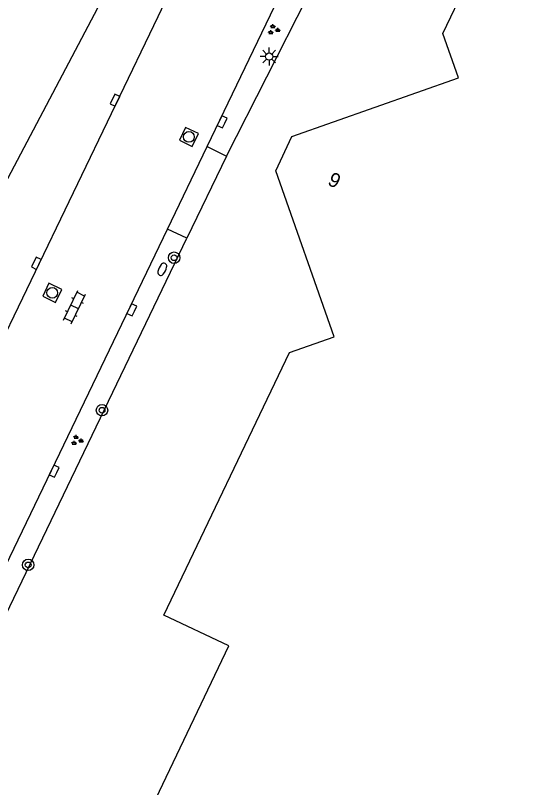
# Model space of a CAD drawing. Extents: x 135999 to 138000, y 396000 to 398501.
# Drawn here: x 136222.5 to 136258.9, y 397886.5 to 397940.3 of the extents above; entities that cross this region are included whole.
import ezdxf

# ---------------------------------------------------------------- set-up
doc = ezdxf.new("R2010")
doc.units = 0
for name, color, linetype in [('gg-afsc-erfafscheiding', 7, 'Continuous'), ('gg-anno-huisnummerreeks BGT', 7, 'Continuous'), ('gg-bbg-hoofdgebouw', 7, 'Continuous'), ('gg-knt-verharding', 7, 'Continuous'), ('gg-knt-verharding nz', 7, 'Continuous'), ('gt-symb-boom', 7, 'Continuous'), ('gt-symb-brandkraan', 7, 'Continuous'), ('gt-symb-groenvak', 7, 'Continuous'), ('gt-symb-klinker verharding', 7, 'Continuous'), ('gt-symb-kolk', 7, 'Continuous'), ('gt-symb-lichtmast', 7, 'Continuous'), ('gt-symb-rioolschacht', 7, 'Continuous')]:
    doc.layers.add(name, color=color, linetype=linetype)

# ---------------------------------------------------------------- blocks, each defined once
blk = doc.blocks.new('gt0-KOLK')
at = {"layer": 'gt-symb-kolk'}
blk.add_lwpolyline([(0, 0), (0.375, 0), (0.375, 0.4), (-0.375, 0.4), (-0.375, 0), (0, 0)], dxfattribs=at)
blk = doc.blocks.new('gt0-RS')
at = {"layer": 'gt-symb-rioolschacht'}
blk.add_lwpolyline([(-0.5, -0.5), (0.5, -0.5), (0.5, 0.5), (-0.5, 0.5)], close=True, dxfattribs=at)
blk.add_circle((0, 0), 0.375, dxfattribs=at)
blk = doc.blocks.new('gt0-BOOM')
at = {"layer": 'gt-symb-boom'}
for radius in [0.4, 0.2]:
    blk.add_circle((0, 0), radius, dxfattribs=at)
blk = doc.blocks.new('gt0-KL1')
at = {"layer": 'gt-symb-klinker verharding'}
for p, q in [((-1.15, 0.3), (1.15, 0.3)), ((-1, -0.3), (-1, 0.3)), ((-0.5, 0.3), (-0.5, 0.45)), ((0, -0.3), (0, 0.3)), ((0.5, 0.3), (0.5, 0.45)), ((1, -0.3), (1, 0.3)), ((-1.15, -0.3), (1.15, -0.3)), ((-0.5, -0.45), (-0.5, -0.3)), ((0.5, -0.45), (0.5, -0.3))]:
    blk.add_line(p, q, dxfattribs=at)
blk = doc.blocks.new('gt0-LMAST')
at = {"layer": 'gt-symb-lichtmast'}
for p, q in [((-0.005, 0.246), (-0.005, 0.621)), ((-0.182, 0.173), (-0.447, 0.438)), ((0.172, 0.173), (0.437, 0.438)), ((-0.255, -0.004), (-0.63, -0.004)), ((-0.182, -0.181), (-0.447, -0.446)), ((-0.005, -0.254), (-0.005, -0.629)), ((0.437, -0.446), (0.172, -0.181)), ((0.245, -0.004), (0.62, -0.004))]:
    blk.add_line(p, q, dxfattribs=at)
blk.add_circle((-0.005, -0.004), 0.25, dxfattribs=at)
blk = doc.blocks.new('gt0-GRVAK')
at = {"layer": 'gt-symb-groenvak'}
for p, q in [((-0.11, 0.189), (-0.228, 0.24)), ((-0.182, 0.153), (0.088, 0.153)), ((-0.091, 0.211), (-0.156, 0.322)), ((-0.047, 0.214), (-0.047, 0.393)), ((-0.004, 0.211), (0.061, 0.322)), ((0.015, 0.189), (0.133, 0.24)), ((0.262, -0.052), (0.197, 0.059)), ((0.305, -0.049), (0.305, 0.13)), ((0.349, -0.052), (0.414, 0.059)), ((-0.245, -0.228), (-0.363, -0.177)), ((-0.318, -0.264), (-0.047, -0.264)), ((-0.226, -0.206), (-0.291, -0.095)), ((-0.183, -0.203), (-0.183, -0.024)), ((-0.139, -0.206), (-0.074, -0.095)), ((-0.12, -0.228), (-0.002, -0.177)), ((0.243, -0.074), (0.125, -0.023)), ((0.17, -0.11), (0.441, -0.11)), ((0.368, -0.074), (0.486, -0.023))]:
    blk.add_line(p, q, dxfattribs=at)
blk = doc.blocks.new('gt0-BR')
at = {"layer": 'gt-symb-brandkraan'}
for centre, radius, start, end in [((-0.244, 0), 0.206, 107.5669, 252.4331), ((0.599, -2.664), 3, 106.892, 107.5669), ((0, -0.691), 0.938, 73.108, 106.892), ((-0.599, -2.664), 3, 72.4331, 73.108), ((0.244, 0), 0.206, 287.567, 72.4331), ((0.599, 2.664), 3, 252.4331, 253.108), ((0, 0.691), 0.938, 253.108, 286.8921), ((-0.599, 2.664), 3, 286.8921, 287.567)]:
    blk.add_arc(centre, radius, start, end, dxfattribs=at)

msp = doc.modelspace()

# ---------------------------------------------------------------- linework, layer by layer
at = {"layer": 'gg-afsc-erfafscheiding'}
for p, q in [((136237.227, 397930.467), (136244.803, 397945.447)), ((136237.227, 397930.467), (136234.44, 397924.749)), ((136220.146, 397895.008), (136234.44, 397924.749))]:
    msp.add_line(p, q, dxfattribs=at)
at = {"layer": 'gg-bbg-hoofdgebouw'}
for points in [[(136211.45, 397918.741), (136215.456, 397916.626), (136231.388, 397946.795), (136231.473, 397946.751), (136234.427, 397952.362), (136205.62, 397967.628)], [(136232.854, 397898.481), (136241.597, 397916.78), (136244.723, 397917.875), (136240.653, 397929.458), (136241.781, 397931.84), (136253.387, 397935.924), (136252.293, 397939.033), (136258.904, 397952.809)], [(136228.402, 397876.936), (136228.167, 397877.048), (136237.375, 397896.321), (136232.854, 397898.481)]]:
    msp.add_lwpolyline(points, dxfattribs=at)
at = {"layer": 'gg-knt-verharding'}
for p, q in [((136235.867, 397931.136), (136243.004, 397945.968)), ((136235.867, 397931.136), (136237.227, 397930.467)), ((136218.796, 397895.656), (136233.094, 397925.372)), ((136234.44, 397924.749), (136233.094, 397925.372))]:
    msp.add_line(p, q, dxfattribs=at)
msp.add_lwpolyline([(136235.762, 397948.336), (136235.427, 397946.862), (136234.923, 397945.437), (136232.433, 397940.178), (136220.589, 397915.633)], dxfattribs=at)
at = {"layer": 'gg-knt-verharding nz'}
msp.add_line((136233.094, 397925.372), (136235.867, 397931.136), dxfattribs=at)

# ---------------------------------------------------------------- block references
at = {"layer": 'gt-symb-boom'}
for p, rotation in [((136233.561, 397923.391), 29.744881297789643), ((136228.537, 397912.756), -115.53973281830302), ((136223.385, 397901.973), -115.53973281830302)]:
    msp.add_blockref('gt0-BOOM', p, dxfattribs=dict(at, rotation=rotation))
at = {"layer": 'gt-symb-brandkraan', "rotation": 64.35692916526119}
msp.add_blockref('gt0-BR', (136232.737, 397922.582), dxfattribs=at)
at = {"layer": 'gt-symb-groenvak'}
for p in [(136240.495, 397939.286), (136226.774, 397910.656)]:
    msp.add_blockref('gt0-GRVAK', p, dxfattribs=at)
at = {"layer": 'gt-symb-klinker verharding', "rotation": 64.28048704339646}
msp.add_blockref('gt0-KL1', (136226.622, 397919.948), dxfattribs=at)
at = {"layer": 'gt-symb-kolk'}
for p, rotation in [((136229.623, 397934.287), 64.35692916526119), ((136237.093, 397932.774), 64.35692916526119), ((136224.137, 397922.917), 64.35692916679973), ((136230.8, 397919.676), 64.35692916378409), ((136225.38, 397908.427), 64.35692916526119)]:
    msp.add_blockref('gt0-KOLK', p, dxfattribs=dict(at, rotation=rotation))
at = {"layer": 'gt-symb-lichtmast'}
msp.add_blockref('gt0-LMAST', (136240.195, 397937.418), dxfattribs=at)
at = {"layer": 'gt-symb-rioolschacht', "rotation": 64.35692916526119}
for p in [(136234.597, 397931.811), (136225.066, 397920.942)]:
    msp.add_blockref('gt0-RS', p, dxfattribs=at)

# ---------------------------------------------------------------- texts
at = {"layer": 'gg-anno-huisnummerreeks BGT'}
msp.add_text('9', height=1, rotation=334.7, dxfattribs=at).set_placement((136244.199, 397928.506))

doc.saveas('drawing.dxf')
